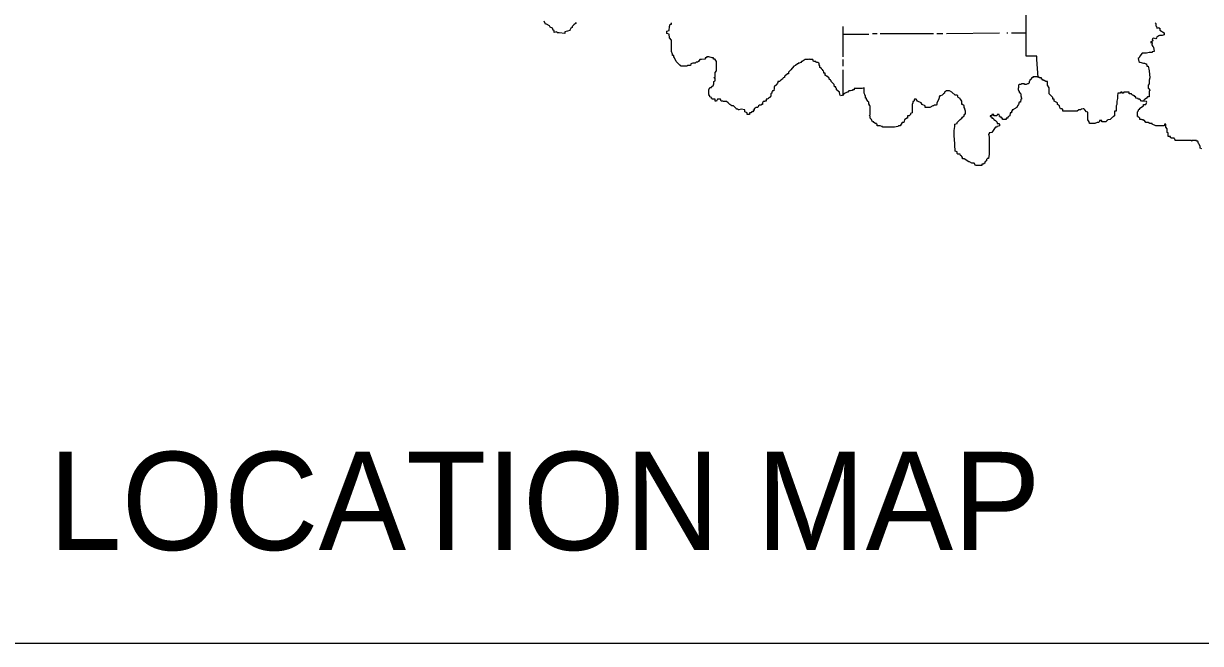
# Model space of a CAD drawing. Extents: x 1458004.1 to 1458040.9, y 194172.7 to 194198.1.
# Drawn here: x 1458012.803 to 1458014.461, y 194177.752 to 194178.625 of the extents above; entities that cross this region are included whole.
import ezdxf

# ---------------------------------------------------------------- set-up
doc = ezdxf.new("R2010")
doc.units = 0
for name, color, linetype in [('State_Map', 7, 'Continuous'), ('Text_11', 7, 'Continuous'), ('Text_Box_16', 7, 'Continuous')]:
    doc.layers.add(name, color=color, linetype=linetype)

msp = doc.modelspace()

# ---------------------------------------------------------------- linework, layer by layer
at = {"layer": 'State_Map'}
for points in [[(1458014.2325, 194178.5492), (1458014.2308, 194178.5742), (1458014.2308, 194178.5792), (1458014.2158, 194178.5792), (1458014.2158, 194178.65)], [(1458013.5817, 194178.6267), (1458013.5808, 194178.625), (1458013.5783, 194178.6233), (1458013.5758, 194178.6208), (1458013.5758, 194178.6192), (1458013.5742, 194178.6183), (1458013.5725, 194178.6158), (1458013.5725, 194178.615), (1458013.5692, 194178.6142), (1458013.5658, 194178.6133), (1458013.5658, 194178.6108), (1458013.5575, 194178.6117), (1458013.555, 194178.6117), (1458013.5542, 194178.6133), (1458013.5508, 194178.6125), (1458013.5508, 194178.615), (1458013.5492, 194178.6158), (1458013.5483, 194178.6183), (1458013.545, 194178.62), (1458013.5442, 194178.6217), (1458013.54, 194178.6242), (1458013.5383, 194178.6242), (1458013.5367, 194178.6283)], [(1458013.7158, 194178.6017), (1458013.7133, 194178.605), (1458013.7125, 194178.61), (1458013.7092, 194178.6108), (1458013.7092, 194178.6142), (1458013.7125, 194178.615), (1458013.7133, 194178.6208), (1458013.7142, 194178.6242), (1458013.7158, 194178.6242), (1458013.7158, 194178.6258)], [(1458013.9575, 194178.6208), (1458013.9575, 194178.5783)], [(1458014.1033, 194178.6108), (1458014.1783, 194178.6117)], [(1458014.1883, 194178.6117), (1458014.19, 194178.6117)], [(1458014.195, 194178.6117), (1458014.2158, 194178.6117)], [(1458014.3975, 194178.6258), (1458014.3983, 194178.625), (1458014.3983, 194178.6217), (1458014.3992, 194178.6208), (1458014.4, 194178.6183), (1458014.4025, 194178.6192), (1458014.4025, 194178.6183), (1458014.4042, 194178.6183), (1458014.4042, 194178.6158), (1458014.41, 194178.6117), (1458014.41, 194178.6092), (1458014.4075, 194178.6083), (1458014.4033, 194178.6083), (1458014.4025, 194178.6075), (1458014.4, 194178.6058), (1458014.3992, 194178.605), (1458014.3983, 194178.6033), (1458014.395, 194178.6042), (1458014.3933, 194178.6033), (1458014.3942, 194178.6008), (1458014.3908, 194178.5983), (1458014.3933, 194178.5983), (1458014.3925, 194178.595), (1458014.3942, 194178.5925), (1458014.395, 194178.5917), (1458014.3958, 194178.5858), (1458014.3933, 194178.585), (1458014.3933, 194178.5842), (1458014.3892, 194178.5842), (1458014.385, 194178.5833), (1458014.3792, 194178.5833), (1458014.3758, 194178.5792), (1458014.375, 194178.5767), (1458014.3733, 194178.5758), (1458014.3742, 194178.5717), (1458014.3758, 194178.5708), (1458014.3808, 194178.5692), (1458014.3825, 194178.5692), (1458014.3842, 194178.5683), (1458014.385, 194178.5683), (1458014.3858, 194178.565), (1458014.3875, 194178.565), (1458014.3892, 194178.5583), (1458014.39, 194178.5483), (1458014.3892, 194178.545), (1458014.3892, 194178.54), (1458014.3875, 194178.5383), (1458014.3875, 194178.5333), (1458014.3892, 194178.5333), (1458014.39, 194178.5308), (1458014.3892, 194178.53), (1458014.3892, 194178.5217), (1458014.3867, 194178.5217), (1458014.385, 194178.52), (1458014.3833, 194178.5183), (1458014.3817, 194178.5175), (1458014.3808, 194178.5158)], [(1458013.8325, 194178.505), (1458013.8325, 194178.5033), (1458013.8308, 194178.5025), (1458013.8308, 194178.5008), (1458013.8292, 194178.5008), (1458013.8292, 194178.5), (1458013.8283, 194178.5), (1458013.8283, 194178.4992), (1458013.8258, 194178.4992), (1458013.8258, 194178.4967), (1458013.8225, 194178.4967), (1458013.8225, 194178.4992), (1458013.8192, 194178.5008), (1458013.8192, 194178.5033), (1458013.8142, 194178.5042), (1458013.8108, 194178.5033), (1458013.81, 194178.5033), (1458013.8092, 194178.5042), (1458013.8075, 194178.5042), (1458013.8075, 194178.505), (1458013.8033, 194178.5092), (1458013.8025, 194178.5092), (1458013.8008, 194178.5092), (1458013.7983, 194178.5108), (1458013.7958, 194178.5133), (1458013.7933, 194178.515), (1458013.79, 194178.515), (1458013.7892, 194178.515), (1458013.7883, 194178.5158), (1458013.7858, 194178.5158), (1458013.785, 194178.5183), (1458013.7808, 194178.5183), (1458013.7792, 194178.5158), (1458013.7775, 194178.5158), (1458013.7775, 194178.5183), (1458013.775, 194178.5183), (1458013.7733, 194178.5183), (1458013.7733, 194178.5192), (1458013.7725, 194178.5192), (1458013.7725, 194178.5208), (1458013.77, 194178.5217), (1458013.77, 194178.5233), (1458013.7692, 194178.5233), (1458013.7692, 194178.525), (1458013.7683, 194178.525), (1458013.7683, 194178.5317), (1458013.77, 194178.535), (1458013.7725, 194178.535), (1458013.7725, 194178.5358), (1458013.775, 194178.5383), (1458013.775, 194178.5392), (1458013.7758, 194178.5392), (1458013.7758, 194178.5433), (1458013.7775, 194178.5442), (1458013.7775, 194178.5483), (1458013.7758, 194178.5483), (1458013.7775, 194178.55), (1458013.7775, 194178.5558), (1458013.7792, 194178.5583), (1458013.7792, 194178.5683), (1458013.7792, 194178.5717), (1458013.7775, 194178.5742), (1458013.7775, 194178.575), (1458013.7758, 194178.575), (1458013.775, 194178.575), (1458013.775, 194178.5767), (1458013.7733, 194178.5767), (1458013.7683, 194178.5783), (1458013.7658, 194178.5783), (1458013.765, 194178.5767), (1458013.7633, 194178.5767), (1458013.7633, 194178.575), (1458013.7583, 194178.5742), (1458013.7558, 194178.5742), (1458013.7542, 194178.5717), (1458013.7525, 194178.5708), (1458013.7508, 194178.5708), (1458013.7508, 194178.57), (1458013.75, 194178.57), (1458013.7492, 194178.5692), (1458013.7458, 194178.5692), (1458013.7433, 194178.5683), (1458013.7425, 194178.5658), (1458013.74, 194178.5658), (1458013.7383, 194178.5658), (1458013.7375, 194178.565), (1458013.7308, 194178.565), (1458013.7292, 194178.565), (1458013.7292, 194178.5658), (1458013.7283, 194178.5658), (1458013.7258, 194178.5683), (1458013.7233, 194178.5708), (1458013.7225, 194178.5717), (1458013.72, 194178.5767), (1458013.7192, 194178.5783), (1458013.7192, 194178.58), (1458013.7175, 194178.58), (1458013.7175, 194178.5817), (1458013.7158, 194178.5858), (1458013.7158, 194178.6017)], [(1458013.9575, 194178.61), (1458013.9942, 194178.61)], [(1458013.9992, 194178.6108), (1458014.0058, 194178.6108)], [(1458014.01, 194178.6108), (1458014.085, 194178.6108)], [(1458014.09, 194178.6108), (1458014.0983, 194178.6108)], [(1458013.9475, 194178.5358), (1458013.9475, 194178.5358), (1458013.9458, 194178.5358), (1458013.945, 194178.5392), (1458013.9408, 194178.5433), (1458013.9408, 194178.5442), (1458013.94, 194178.545), (1458013.9383, 194178.5467), (1458013.9383, 194178.5483), (1458013.9375, 194178.5483), (1458013.935, 194178.5508), (1458013.9342, 194178.5508), (1458013.9342, 194178.5508), (1458013.9333, 194178.5517), (1458013.9325, 194178.5517), (1458013.9325, 194178.555), (1458013.9308, 194178.555), (1458013.9308, 194178.5567), (1458013.93, 194178.5583), (1458013.9292, 194178.5583), (1458013.9292, 194178.56), (1458013.9283, 194178.56), (1458013.9283, 194178.56), (1458013.9275, 194178.5617), (1458013.925, 194178.5633), (1458013.925, 194178.5658), (1458013.9242, 194178.5658), (1458013.9242, 194178.5692), (1458013.9233, 194178.5692), (1458013.9225, 194178.57), (1458013.92, 194178.57), (1458013.92, 194178.5708), (1458013.9192, 194178.5708), (1458013.9192, 194178.5717), (1458013.9175, 194178.5717), (1458013.9158, 194178.5717), (1458013.915, 194178.5742), (1458013.9108, 194178.5742), (1458013.91, 194178.575), (1458013.9083, 194178.5742), (1458013.9042, 194178.5742), (1458013.9, 194178.5717), (1458013.8992, 194178.5717), (1458013.8983, 194178.57), (1458013.8983, 194178.57), (1458013.8958, 194178.5692), (1458013.8942, 194178.5692), (1458013.8942, 194178.5683), (1458013.8933, 194178.5683), (1458013.8908, 194178.5658), (1458013.8883, 194178.565), (1458013.8842, 194178.56), (1458013.8808, 194178.5567), (1458013.8808, 194178.5542), (1458013.8792, 194178.5542), (1458013.8758, 194178.5508), (1458013.875, 194178.5508), (1458013.875, 194178.5492), (1458013.8733, 194178.5483), (1458013.8725, 194178.5467), (1458013.87, 194178.545), (1458013.8683, 194178.5433), (1458013.8658, 194178.5433), (1458013.8658, 194178.5408), (1458013.865, 194178.5408), (1458013.8642, 194178.5392), (1458013.8608, 194178.5358), (1458013.8608, 194178.5333), (1458013.86, 194178.5308), (1458013.86, 194178.53), (1458013.8583, 194178.53), (1458013.8575, 194178.5283), (1458013.8575, 194178.5267), (1458013.8558, 194178.5258), (1458013.8558, 194178.5233), (1458013.855, 194178.5208), (1458013.8542, 194178.5208), (1458013.8525, 194178.52), (1458013.8525, 194178.5192), (1458013.8508, 194178.5183), (1458013.8492, 194178.5183), (1458013.8492, 194178.5158), (1458013.8475, 194178.5158), (1458013.8475, 194178.515), (1458013.845, 194178.515), (1458013.8442, 194178.5133), (1458013.8442, 194178.5108), (1458013.8425, 194178.5108), (1458013.8425, 194178.51), (1458013.84, 194178.51), (1458013.8383, 194178.5092), (1458013.8375, 194178.5067), (1458013.835, 194178.5067), (1458013.8325, 194178.505), (1458013.8325, 194178.5033), (1458013.8308, 194178.5017), (1458013.8308, 194178.5008), (1458013.8292, 194178.5008), (1458013.8292, 194178.5), (1458013.8283, 194178.5), (1458013.8283, 194178.4992)], [(1458013.9575, 194178.5742), (1458013.9575, 194178.565)], [(1458013.9575, 194178.56), (1458013.9575, 194178.5233)], [(1458014.2733, 194178.5017), (1458014.2675, 194178.5017), (1458014.2675, 194178.5042), (1458014.2658, 194178.5042), (1458014.2658, 194178.505), (1458014.2642, 194178.505), (1458014.2633, 194178.5067), (1458014.2625, 194178.5092), (1458014.26, 194178.5108), (1458014.26, 194178.5133), (1458014.255, 194178.5158), (1458014.255, 194178.5183), (1458014.2533, 194178.5183), (1458014.2533, 194178.5208), (1458014.2525, 194178.5217), (1458014.2483, 194178.5258), (1458014.2483, 194178.5342), (1458014.2458, 194178.5383), (1458014.2458, 194178.5433), (1458014.245, 194178.5433), (1458014.2433, 194178.5433), (1458014.2425, 194178.5442), (1458014.2408, 194178.5442), (1458014.2408, 194178.545), (1458014.2392, 194178.545), (1458014.2383, 194178.5467), (1458014.2375, 194178.5467), (1458014.2375, 194178.5483), (1458014.2358, 194178.5483), (1458014.2342, 194178.5483), (1458014.2342, 194178.5492), (1458014.2325, 194178.55), (1458014.225, 194178.55), (1458014.225, 194178.5483), (1458014.2233, 194178.5483), (1458014.2225, 194178.5467), (1458014.2208, 194178.545), (1458014.2208, 194178.5442), (1458014.22, 194178.5433), (1458014.22, 194178.5408), (1458014.2192, 194178.5408), (1458014.2183, 194178.54), (1458014.2175, 194178.54), (1458014.2158, 194178.5392), (1458014.2133, 194178.5392), (1458014.2133, 194178.54), (1458014.2108, 194178.54), (1458014.2092, 194178.54), (1458014.2083, 194178.5392), (1458014.2058, 194178.5392), (1458014.205, 194178.5383), (1458014.205, 194178.535), (1458014.205, 194178.5342), (1458014.2042, 194178.5342), (1458014.2042, 194178.5317), (1458014.205, 194178.5308), (1458014.205, 194178.53), (1458014.2058, 194178.53), (1458014.2058, 194178.5283), (1458014.2075, 194178.5267), (1458014.2083, 194178.525), (1458014.2083, 194178.5233), (1458014.2092, 194178.52), (1458014.2092, 194178.5183), (1458014.2083, 194178.5183), (1458014.2075, 194178.5142), (1458014.2058, 194178.5142), (1458014.205, 194178.5108), (1458014.2033, 194178.5092), (1458014.2025, 194178.5067), (1458014.1983, 194178.5042), (1458014.1975, 194178.5033), (1458014.1958, 194178.5033), (1458014.1958, 194178.5017), (1458014.195, 194178.5017), (1458014.195, 194178.4992), (1458014.1933, 194178.4992), (1458014.1925, 194178.495), (1458014.1908, 194178.4942), (1458014.19, 194178.4933), (1458014.19, 194178.4917), (1458014.1875, 194178.4917), (1458014.1875, 194178.49), (1458014.1825, 194178.49), (1458014.1825, 194178.4917), (1458014.1808, 194178.4917), (1458014.1808, 194178.4933), (1458014.1792, 194178.4933), (1458014.1792, 194178.4942), (1458014.1783, 194178.4942), (1458014.1783, 194178.495), (1458014.1775, 194178.4967), (1458014.175, 194178.4967), (1458014.1742, 194178.495), (1458014.17, 194178.495), (1458014.17, 194178.4967), (1458014.1675, 194178.4967), (1458014.1675, 194178.495), (1458014.165, 194178.495), (1458014.165, 194178.4942), (1458014.1675, 194178.4933)], [(1458014.0575, 194178.515), (1458014.0558, 194178.515), (1458014.0558, 194178.5133), (1458014.055, 194178.5108), (1458014.055, 194178.4992), (1458014.0525, 194178.4983), (1458014.0525, 194178.4967), (1458014.0508, 194178.495), (1458014.0483, 194178.495), (1458014.0483, 194178.4917), (1458014.0475, 194178.4917), (1458014.0442, 194178.4892), (1458014.0433, 194178.4858), (1458014.0408, 194178.4858), (1458014.0383, 194178.4808), (1458014.0358, 194178.4808), (1458014.035, 194178.48), (1458014.03, 194178.4792), (1458014.0233, 194178.4792), (1458014.0175, 194178.4792), (1458014.015, 194178.4792), (1458014.0133, 194178.4792), (1458014.0133, 194178.48), (1458014.0125, 194178.48), (1458014.01, 194178.4808), (1458014.0058, 194178.4808), (1458014.0058, 194178.4833), (1458014.005, 194178.4833), (1458014.005, 194178.4842), (1458014.0033, 194178.4842), (1458014.0008, 194178.4858), (1458014.0008, 194178.4867), (1458013.9992, 194178.4867), (1458013.9975, 194178.49), (1458013.9958, 194178.4917), (1458013.9958, 194178.495), (1458013.995, 194178.495), (1458013.9958, 194178.4967), (1458013.9958, 194178.5092), (1458013.995, 194178.5092), (1458013.995, 194178.5108), (1458013.9942, 194178.5108), (1458013.9942, 194178.5142), (1458013.9925, 194178.515), (1458013.9925, 194178.5158), (1458013.9908, 194178.5183), (1458013.9908, 194178.52), (1458013.9892, 194178.52), (1458013.9892, 194178.5217), (1458013.9892, 194178.5233), (1458013.9883, 194178.5242), (1458013.9883, 194178.525), (1458013.9875, 194178.5267), (1458013.9875, 194178.5342), (1458013.9842, 194178.5333), (1458013.975, 194178.5333), (1458013.9733, 194178.5333), (1458013.9733, 194178.5317), (1458013.9708, 194178.5317), (1458013.9708, 194178.5308), (1458013.97, 194178.5308), (1458013.9683, 194178.53), (1458013.9658, 194178.53), (1458013.9642, 194178.5283), (1458013.9633, 194178.5283), (1458013.9608, 194178.5267), (1458013.9592, 194178.5258), (1458013.9575, 194178.5242), (1458013.9542, 194178.5233), (1458013.9533, 194178.525), (1458013.9533, 194178.5258), (1458013.9525, 194178.5267), (1458013.9525, 194178.5283), (1458013.9483, 194178.5317), (1458013.9483, 194178.5333), (1458013.9475, 194178.5342), (1458013.9475, 194178.5358)], [(1458014.1708, 194178.4767), (1458014.1708, 194178.4758), (1458014.17, 194178.4758), (1458014.1692, 194178.4742), (1458014.1675, 194178.4717), (1458014.165, 194178.4708), (1458014.1633, 194178.4708), (1458014.1633, 194178.4692), (1458014.1625, 194178.4692), (1458014.1633, 194178.465), (1458014.1633, 194178.4408), (1458014.1625, 194178.435), (1458014.1608, 194178.435), (1458014.1608, 194178.4342), (1458014.16, 194178.4333), (1458014.16, 194178.4317), (1458014.1583, 194178.4308), (1458014.1583, 194178.4308), (1458014.1575, 194178.43), (1458014.1575, 194178.4283), (1458014.155, 194178.4267), (1458014.1533, 194178.4267), (1458014.1533, 194178.425), (1458014.1458, 194178.425), (1458014.1442, 194178.425), (1458014.1425, 194178.4283), (1458014.1392, 194178.4283), (1458014.1358, 194178.43), (1458014.135, 194178.43), (1458014.1283, 194178.4342), (1458014.1258, 194178.4342), (1458014.1258, 194178.4367), (1458014.125, 194178.4367), (1458014.125, 194178.4383), (1458014.1233, 194178.4392), (1458014.1225, 194178.4408), (1458014.1192, 194178.4408), (1458014.1183, 194178.4417), (1458014.1183, 194178.4442), (1458014.1158, 194178.445), (1458014.1158, 194178.4483), (1458014.115, 194178.4508), (1458014.115, 194178.4558), (1458014.1142, 194178.4667), (1458014.1142, 194178.4742), (1458014.115, 194178.48), (1458014.115, 194178.4833), (1458014.1183, 194178.4842), (1458014.1183, 194178.4858), (1458014.1225, 194178.49), (1458014.125, 194178.4917), (1458014.1258, 194178.4933), (1458014.1283, 194178.495), (1458014.1283, 194178.4967), (1458014.1292, 194178.4967), (1458014.13, 194178.4983), (1458014.13, 194178.5017), (1458014.1292, 194178.5042), (1458014.1292, 194178.5058), (1458014.1283, 194178.5058), (1458014.1283, 194178.5092), (1458014.1258, 194178.5108), (1458014.125, 194178.5108), (1458014.125, 194178.515), (1458014.125, 194178.5158), (1458014.1233, 194178.5183), (1458014.1225, 194178.5183), (1458014.1225, 194178.5192), (1458014.12, 194178.5208), (1458014.12, 194178.5208), (1458014.1192, 194178.5217), (1458014.1192, 194178.5233), (1458014.1183, 194178.5242), (1458014.1158, 194178.5242), (1458014.1108, 194178.5283), (1458014.1075, 194178.53), (1458014.1033, 194178.53), (1458014.1008, 194178.5283), (1458014.1008, 194178.5267), (1458014.0992, 194178.5258), (1458014.0975, 194178.5242), (1458014.095, 194178.5233), (1458014.0942, 194178.5233), (1458014.0933, 194178.5217), (1458014.0933, 194178.52), (1458014.0925, 194178.5192), (1458014.0925, 194178.5183), (1458014.09, 194178.5133), (1458014.09, 194178.5108), (1458014.0892, 194178.5108), (1458014.0892, 194178.51), (1458014.0858, 194178.51), (1458014.085, 194178.5092), (1458014.0842, 194178.5092), (1458014.08, 194178.5067), (1458014.0733, 194178.5067), (1458014.0733, 194178.5092), (1458014.0692, 194178.5108), (1458014.0675, 194178.5133), (1458014.0625, 194178.5158), (1458014.0608, 194178.5183)], [(1458014.0608, 194178.5183), (1458014.0583, 194178.5183), (1458014.0575, 194178.515)], [(1458014.41, 194178.4808), (1458014.3983, 194178.4808), (1458014.3933, 194178.4833), (1458014.3933, 194178.4842), (1458014.39, 194178.4842), (1458014.3875, 194178.4858), (1458014.3842, 194178.4858), (1458014.3825, 194178.4883), (1458014.3808, 194178.4883), (1458014.3808, 194178.4892), (1458014.3792, 194178.4892), (1458014.3783, 194178.49), (1458014.3758, 194178.49), (1458014.3758, 194178.4917), (1458014.3742, 194178.4933), (1458014.3733, 194178.4933), (1458014.3733, 194178.4942), (1458014.3725, 194178.4942), (1458014.3725, 194178.5008), (1458014.3733, 194178.5017), (1458014.3742, 194178.5042), (1458014.3758, 194178.5042), (1458014.3758, 194178.5058), (1458014.3808, 194178.5092), (1458014.3808, 194178.5108), (1458014.3842, 194178.5108), (1458014.385, 194178.5133), (1458014.3858, 194178.5142), (1458014.385, 194178.515), (1458014.3808, 194178.5158), (1458014.3783, 194178.5158), (1458014.3758, 194178.5183), (1458014.3733, 194178.5183), (1458014.3733, 194178.5192), (1458014.37, 194178.52), (1458014.37, 194178.5217), (1458014.3692, 194178.5217), (1458014.3683, 194178.5233), (1458014.3675, 194178.5233), (1458014.3658, 194178.5242), (1458014.365, 194178.5242), (1458014.3642, 194178.5258), (1458014.3608, 194178.5258), (1458014.3608, 194178.5283), (1458014.3533, 194178.5283), (1458014.3525, 194178.5267), (1458014.3508, 194178.5267), (1458014.3508, 194178.5283), (1458014.3492, 194178.5283), (1458014.3483, 194178.5267), (1458014.345, 194178.5267), (1458014.345, 194178.5258), (1458014.3442, 194178.5242), (1458014.3442, 194178.5192), (1458014.3433, 194178.5158), (1458014.3433, 194178.5108), (1458014.3425, 194178.5092), (1458014.3425, 194178.5017), (1458014.34, 194178.5017), (1458014.34, 194178.4967), (1458014.34, 194178.495), (1458014.3392, 194178.495), (1458014.3392, 194178.4942), (1458014.3375, 194178.4933), (1458014.3342, 194178.49), (1458014.3308, 194178.4892), (1458014.33, 194178.4883), (1458014.3292, 194178.4883), (1458014.3283, 194178.4867), (1458014.3225, 194178.4867), (1458014.3225, 194178.4883), (1458014.3192, 194178.4883), (1458014.3192, 194178.4867), (1458014.3183, 194178.4867), (1458014.3175, 194178.4858), (1458014.3158, 194178.4858), (1458014.3125, 194178.4842), (1458014.3058, 194178.4842), (1458014.305, 194178.4842), (1458014.305, 194178.4858), (1458014.3042, 194178.4858), (1458014.3042, 194178.4867), (1458014.3025, 194178.4892), (1458014.3025, 194178.5), (1458014.3008, 194178.5008), (1458014.2983, 194178.5033), (1458014.2975, 194178.5042), (1458014.2975, 194178.505), (1458014.2958, 194178.505), (1458014.2942, 194178.5042), (1458014.2933, 194178.5042), (1458014.2925, 194178.5033), (1458014.29, 194178.5033), (1458014.2875, 194178.5017), (1458014.2733, 194178.5017)], [(1458013.8283, 194178.4992), (1458013.8258, 194178.4992), (1458013.8258, 194178.4967), (1458013.8225, 194178.4967), (1458013.8225, 194178.4992), (1458013.8192, 194178.5008), (1458013.8192, 194178.5033)], [(1458014.1675, 194178.4933), (1458014.1675, 194178.4917), (1458014.1692, 194178.4917), (1458014.17, 194178.49), (1458014.1725, 194178.4883), (1458014.1742, 194178.4867), (1458014.1742, 194178.4858), (1458014.175, 194178.4858), (1458014.175, 194178.4842), (1458014.1775, 194178.4842), (1458014.1775, 194178.4833), (1458014.1783, 194178.4833), (1458014.1783, 194178.4808), (1458014.175, 194178.48), (1458014.1742, 194178.48), (1458014.1742, 194178.4792), (1458014.1725, 194178.4792), (1458014.1708, 194178.4767)], [(1458014.4633, 194178.4483), (1458014.4608, 194178.4492), (1458014.4608, 194178.4517), (1458014.4592, 194178.455), (1458014.4583, 194178.4558), (1458014.4575, 194178.4592), (1458014.4558, 194178.4592), (1458014.4558, 194178.46), (1458014.4542, 194178.46), (1458014.4508, 194178.46), (1458014.4492, 194178.46), (1458014.4492, 194178.4592), (1458014.4483, 194178.46), (1458014.4258, 194178.46), (1458014.4258, 194178.4617), (1458014.425, 194178.4617), (1458014.4242, 194178.4633), (1458014.4208, 194178.4633), (1458014.42, 194178.4633), (1458014.42, 194178.4642), (1458014.4192, 194178.4642), (1458014.4192, 194178.465), (1458014.4192, 194178.4658), (1458014.4158, 194178.4658), (1458014.4158, 194178.4708), (1458014.4142, 194178.4717), (1458014.4142, 194178.4767), (1458014.4125, 194178.4792), (1458014.4125, 194178.4833), (1458014.4108, 194178.4833), (1458014.41, 194178.4808)]]:
    msp.add_lwpolyline(points, dxfattribs=at)
at = {"layer": 'Text_Box_16'}
msp.add_line((1458015.7858, 194177.7517), (1458011.3458, 194177.7517), dxfattribs=at)

# ---------------------------------------------------------------- texts
at = {"layer": 'Text_11'}
msp.add_text('LOCATION MAP', height=0.138335, dxfattribs=at).set_placement((1458012.8383, 194177.8833))

doc.saveas('drawing.dxf')
